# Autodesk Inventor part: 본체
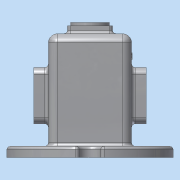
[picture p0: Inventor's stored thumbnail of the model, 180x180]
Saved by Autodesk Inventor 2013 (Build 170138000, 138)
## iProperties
Created: 2018-07
Part Number: 본체
Material: 알루미늄 6061
Document SubType Name: Modeling
Designer: Administrator
Density: 2.71 g/cm^3
Mass: 910.07 g
Surface Area: 1013.39 cm^2
Volume: 335.819 cm^3
Author: Administrator
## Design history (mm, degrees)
sketch "스케치1"
  geometry: L1 (-37, 37)-(37, 37); L2 (37, 37)-(37, -37); L3 (37, -37)-(-37, -37); L4 (-37, -37)-(-37, 37); L5 (-37, 37)-(37, -37); L6 (37, 37)-(-37, -37); 1 further point
  constraints: 12 end point, 2 midpoint, 2 parallel, 1 horizontal, 1 perpendicular
  dimensions: "d0" = 74 distance of L2.end L3.end; "d1" = 74 distance of L1.end L2.end
extrude "돌출1" new body sketch "스케치1" stored distance "d2" = 100; taper "d3" = 0 deg
sketch "스케치2"
  geometry: C1 r 75 at (0, 0); 1 further point
  constraints: 1 centre point, 1 coincident
  dimensions: "d4" = 150 diameter of C1
extrude "돌출2" join sketch "스케치2" distance "d6" = 10; taper "d7" = 0 deg
fillet "모깎기1" dims "d8" = 8
fillet "모깎기2" dims "d9" = 8
sketch "스케치3"
  geometry: L1 (-32, 32)-(32, 32); L2 (32, 32)-(32, -32); L3 (32, -32)-(-32, -32); L4 (-32, -32)-(-32, 32); L5 (-32, 32)-(32, -32); L6 (32, 32)-(-32, -32); C1 r 75 at (0, 0) reference
  constraints: 12 end point, 2 midpoint, 2 parallel, 1 horizontal, 1 perpendicular
  dimensions: "d10" = 64 distance of L2.end L3.end; "d11" = 64 distance of L1.end L2.end
extrude "돌출3" cut sketch "스케치3" distance "d12" = 105; taper "d13" = 0 deg
fillet "모깎기3" dims "d14" = 3
fillet "모깎기4" dims "d15" = 3
fillet "모깎기5" dims "d16" = 3
sketch "스케치4"
  geometry: C1 r 10 at (0, 75); 1 further point
  constraints: 2 vertical alignment, 1 centre point, 1 other
  dimensions: "d17" = 20 diameter of C1
extrude "돌출4" cut sketch "스케치4" stored distance "d18" = 105; taper "d19" = 0 deg
fillet "모깎기6" dims "d23" = 3
fillet "모깎기7" dims "d24" = 3
sketch "스케치5"
  geometry: L1 (42, 32)-(-60, 32) reference; L2 (-5, 32)-(20, 32); L3 (20, 32)-(17.452, 25); L4 (17.452, 25)-(-5, 25); L5 (-5, 25)-(-5, 32); L6 (-60, 73.889)-(-60, 12.862) reference; 1 further point
  constraints: 8 end point, 2 point on line, 1 parallel, 1 perpendicular
  dimensions: "d25" = 25 distance of L2.start L2.end; "d27" = 70 deg angle of L2 L3; "d73" = 55 distance between parallel lines of L6 L5; "d74" = 7 distance between parallel lines of L4 L1
revolve "회전1" sketch "스케치5" stored, may be unused: angle "d29" = 90 deg
sketch "스케치6"
  geometry: L1 (4, -22)-(54, -22); L2 (54, -22)-(54, -72); L3 (54, -72)-(4, -72); L4 (4, -72)-(4, -22); L5 (4, -22)-(54, -72); L6 (54, -22)-(4, -72); L7 (41.862, -102)-(102.889, -102) reference; 3 further points
  constraints: 12 end point, 3 midpoint, 2 parallel, 1 horizontal, 1 perpendicular, 1 vertical alignment
  dimensions: "d30" = 50 distance of L2.end L3.end; "d31" = 50 distance of L1.end L2.end; "d69" = 55 distance from line of point (29, -47) L7
extrude "돌출5" join sketch "스케치6" distance "d32" = 13; taper "d33" = 0 deg
node "작업 평면1"
sketch "스케치7"
  geometry: C1 r 17.5 at (0, 0); 1 further point
  constraints: 1 centre point, 1 coincident
  dimensions: "d35" = 35 diameter of C1
extrude "돌출6" join sketch "스케치7" distance "d36" = 3; taper "d37" = 0 deg
sketch "스케치8"
  geometry: L1 (-20, 20)-(20, 20); L2 (20, 20)-(20, -20); L3 (20, -20)-(-20, -20); L4 (-20, -20)-(-20, 20); L5 (-20, 20)-(20, -20); L6 (20, 20)-(-20, -20); C1 r 17.5 at (0, 0) reference
  constraints: 12 end point, 2 midpoint, 2 parallel, 1 horizontal, 1 perpendicular
  dimensions: "d38" = 40 distance of L2.end L3.end; "d39" = 40 distance of L1.end L2.end
extrude "돌출7" join sketch "스케치8" distance "d40" = 7; taper "d41" = 0 deg
sketch "스케치9"
  geometry: L1 (41.862, -102)-(102.889, -102) reference; C1 r 16 at (29, -47); 2 further points
  constraints: 1 centre point, 1 coincident, 1 vertical alignment
  dimensions: "d42" = 32 diameter of C1; "d70" = 55 distance from line of L1 point (29, -47)
extrude "돌출8" cut sketch "스케치9" stored distance "d43" = 7; taper "d44" = 0 deg
sketch "스케치10"
  geometry: C1 r 17.5 at (0, 0) reference; C2 r 14 at (0, 0)
  constraints: 1 centre point, 1 coincident
  dimensions: "d45" = 28 diameter of C2
extrude "돌출9" cut sketch "스케치10" distance "d46" = 4; taper "d47" = 0 deg
sketch "스케치11"
  geometry: C1 r 14 at (0, 0) reference; C2 r 10.5 at (0, 0)
  constraints: 1 centre point, 1 coincident
  dimensions: "d48" = 21 diameter of C2
extrude "돌출10" cut sketch "스케치11" stored distance "d49" = 4; taper "d50" = 0 deg
fillet "모깎기10" dims "d53" = 6
fillet "모깎기11" dims "d54" = 6
fillet "모깎기12" dims "d55" = 3
fillet "모깎기13" dims "d56" = 3
fillet "모깎기14" dims "d57" = 3
chamfer "모따기1" distance "d58" = 1; stored, may be unused: second distance "d59" = 2, angle "d60" = 45 deg
sketch "스케치12"
  geometry: A1 r 6 centre (48, -28) between (54, -28) and (48, -22) reference; A2 r 6 centre (10, -28) between (10, -22) and (4, -28) reference; A3 r 6 centre (10, -66) between (4, -66) and (10, -72) reference; A4 r 6 centre (48, -66) between (48, -72) and (54, -66) reference; 4 further points
  constraints: 4 coincident
hole "구멍1" sketch "스케치12" at (10, -28), (48, -28), (48, -66), (10, -66) diameter "d61" = 3.242; stored, may be unused: countersink angle "d65" = 90 deg, drill point angle "d67" = 118 deg; dims "d62" = 8, "d63" = 4, "d64" = 2, "d66" = 10
sketch "스케치13"
  geometry: L1 (11.5, 18)-(46.5, 18) reference; 2 further points
  constraints: 1 vertical alignment, 1 other
  dimensions: "d68" = 30 distance from line of L1 point (29, -12)
feature "엠보싱1" sketch "스케치13" dims "d71" = 0.5, "d72" = 0
node "솔리드1"
pattern_circular "원형 패턴1" dims angle "d21" = 360 deg
mirror "대칭1"
mirror "대칭2"
mirror "대칭3"
